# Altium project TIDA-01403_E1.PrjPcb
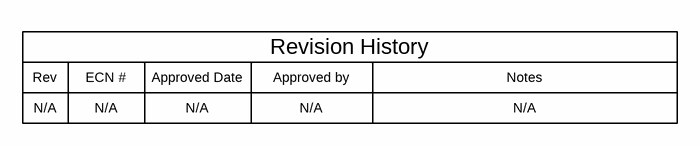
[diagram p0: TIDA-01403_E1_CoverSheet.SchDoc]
TID: TIDA-01403; TechSupport: http://www.ti.com/support; SCH_Rev: E1; PRJ_Title: 74-dB SNR, 10-MSPS, 14-Bit, Analog Front-End Reference Design for QVGA Resolution Thermal Imaging Cameras; PRJ_Number: TIDA-01403; PRJ_Engineer: Sharad Yadav; PRJ_Customer: Public Release; PCB_Rev: E1; PCB_Layout: Sharad Yadav; CopyrightYear: 2017
4 sheets, 161 parts. Net scope: flat (ports and power ports of the same name join across sheets).
Board file: TIDA-01403_E1.PcbDoc
Sheets:
  TIDA-01403_E1_CoverSheet.SchDoc
  TIDA-01403_E1_SchSheet_2.SchDoc
  TIDA-01403_E1_EVM_Hardware.SchDoc
  TIDA-01403_E1_SchSheet_1.SchDoc

## Sheet TIDA-01403_E1_CoverSheet.SchDoc: System Block Diagram
size 431 x 279 mm; Date: Not shown in title block; ApprovedBy: Not shown in title block; CheckedBy: Not shown in title block; Author: Not shown in title block; CompanyName: Not shown in title block; DrawnBy: Sharad Yadav; Engineer: Not shown in title block; Organization: Not shown in title block; Address1: Not shown in title block; Address2: Not shown in title block; Address3: Not shown in title block; Address4: Not shown in title block; DocumentNumber: 1; Revision: Use project parameter SCH_Rev; SheetNumber: 1; SheetTotal: 4; PageSetup: Record=PageOptions¦CenterHorizontal=True¦CenterVertical=True¦PrintScale=1.00¦XCorrection=1.00¦YCorrection=1.00¦PrintKind=0¦BorderSize=5000000¦LeftOffset=0¦BottomOffset=0¦Orientation=2¦PaperLength=1000¦PaperWidth=1000¦Scale=100¦PaperSource=15¦PrintQuality=600¦MediaType=1¦DitherType=10¦PaperKind=Letter¦PrintScaleMode=1

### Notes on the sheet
- Rev
- N/A
- ECN #
- Approved Date
- Approved by
- Revision History
- Notes

## Sheet TIDA-01403_E1_SchSheet_2.SchDoc: LDO, Status LEDs and Connectors
size 431 x 279 mm; Date: Not shown in title block; ApprovedBy: Not shown in title block; CheckedBy: Not shown in title block; Author: Not shown in title block; CompanyName: Not shown in title block; DrawnBy: Sharad Yadav; Engineer: Not shown in title block; Organization: Not shown in title block; Address1: Not shown in title block; Address2: Not shown in title block; Address3: Not shown in title block; Address4: Not shown in title block; DocumentNumber: 1; Revision: Use project parameter SCH_Rev; SheetNumber: 3; SheetTotal: 4; PageSetup: Record=PageOptions¦CenterHorizontal=True¦CenterVertical=True¦PrintScale=1.00¦XCorrection=1.00¦YCorrection=1.00¦PrintKind=0¦BorderSize=5000000¦LeftOffset=0¦BottomOffset=0¦Orientation=2¦PaperLength=1000¦PaperWidth=1000¦Scale=100¦PaperSource=15¦PrintQuality=600¦MediaType=1¦DitherType=10¦PaperKind=Letter¦PrintScaleMode=1
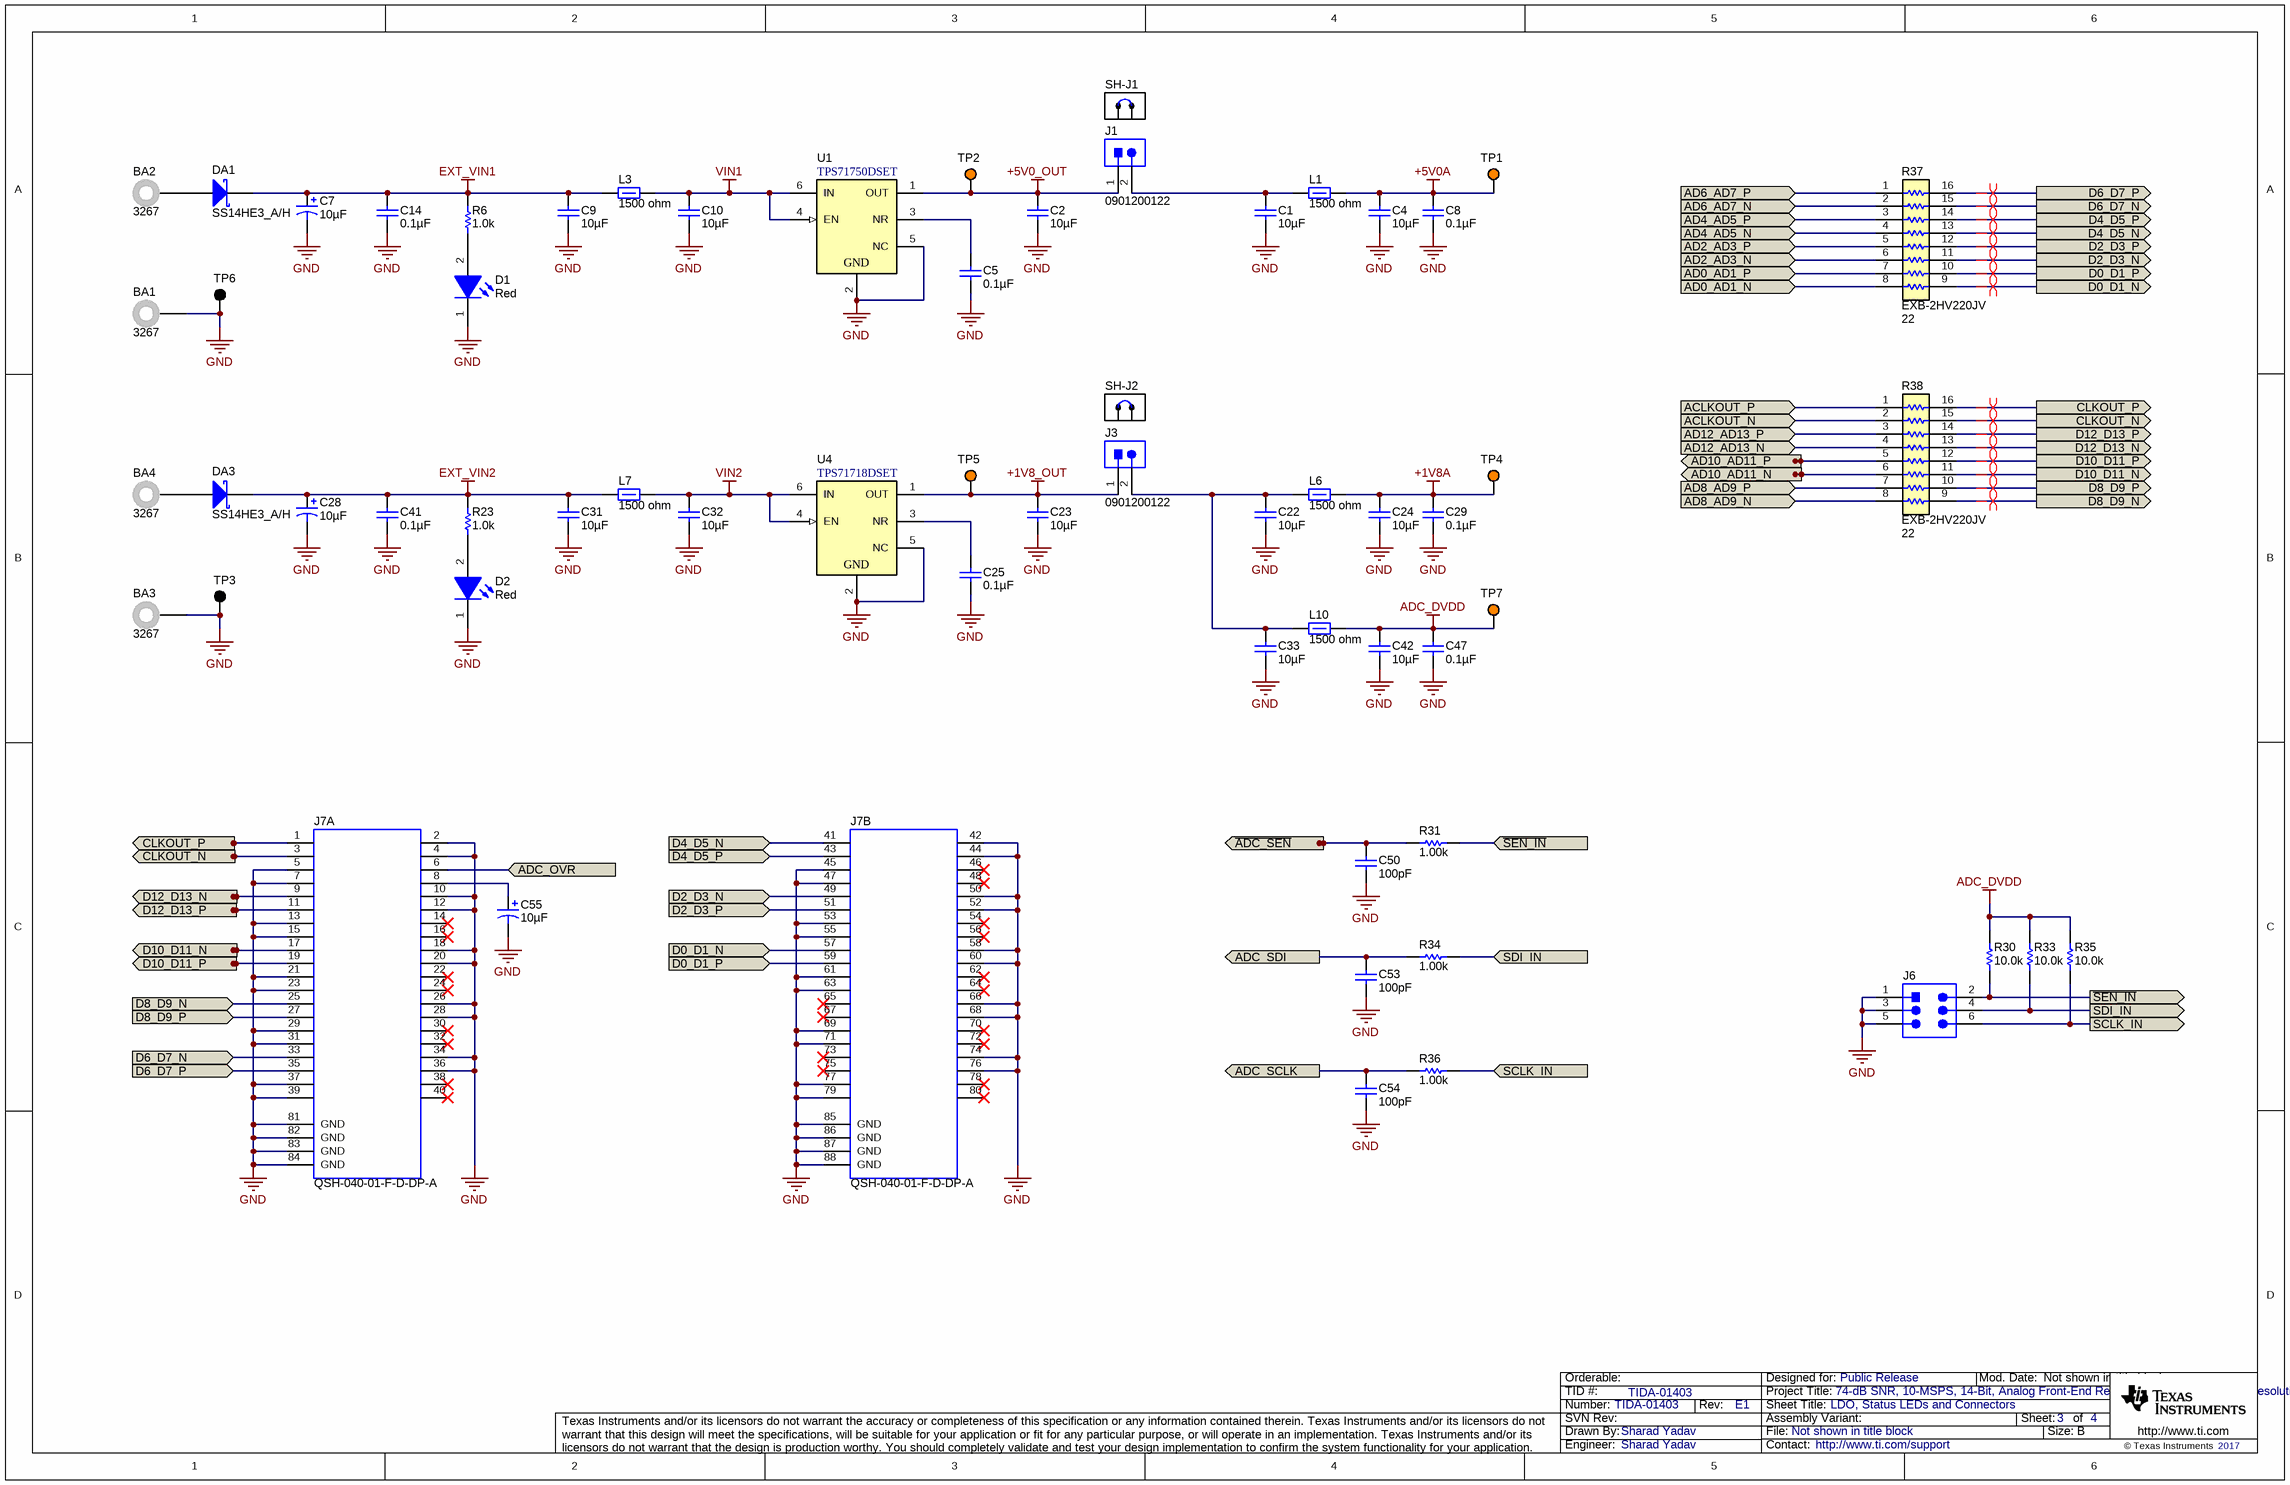
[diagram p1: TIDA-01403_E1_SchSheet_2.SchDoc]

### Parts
(Parts that share a designator on the sheet are numbered #1, #2 ... from top to bottom, then left to right.)
BA1  3267  [Pomona_3267]
BA2  3267  [Pomona_3267]
BA3  3267  [Pomona_3267]
BA4  3267  [Pomona_3267]
C1  ValueDisplayed: 10µF  [0805_HV]  (hidden comment: EMK212BB7106MG-T)
C2  ValueDisplayed: 10µF  [0805_HV]  (hidden comment: EMK212BB7106MG-T)
C4  ValueDisplayed: 10µF  [0805_HV]  (hidden comment: EMK212BB7106MG-T)
C5  ValueDisplayed: 0.1µF  [0402S]  (hidden comment: GRM155R71E104KE14D)
C7  ValueDisplayed: 10µF  [6032-28]  (hidden comment: 593D106X9016C2TE3)
C8  ValueDisplayed: 0.1µF  [0402S]  (hidden comment: GRM155R71C104KA88D)
C9  ValueDisplayed: 10µF  [0805_HV]  (hidden comment: EMK212BB7106MG-T)
C10  ValueDisplayed: 10µF  [0805_HV]  (hidden comment: EMK212BB7106MG-T)
C14  ValueDisplayed: 0.1µF  [0402S]  (hidden comment: GRM155R71C104KA88D)
C22  ValueDisplayed: 10µF  [0805_HV]  (hidden comment: EMK212BB7106MG-T)
C23  ValueDisplayed: 10µF  [0805_HV]  (hidden comment: EMK212BB7106MG-T)
C24  ValueDisplayed: 10µF  [0805_HV]  (hidden comment: EMK212BB7106MG-T)
C25  ValueDisplayed: 0.1µF  [0402S]  (hidden comment: GRM155R71E104KE14D)
C28  ValueDisplayed: 10µF  [6032-28]  (hidden comment: 593D106X9016C2TE3)
C29  ValueDisplayed: 0.1µF  [0402S]  (hidden comment: GRM155R71C104KA88D)
C31  ValueDisplayed: 10µF  [0805_HV]  (hidden comment: EMK212BB7106MG-T)
C32  ValueDisplayed: 10µF  [0805_HV]  (hidden comment: EMK212BB7106MG-T)
C33  ValueDisplayed: 10µF  [0805_HV]  (hidden comment: EMK212BB7106MG-T)
C41  ValueDisplayed: 0.1µF  [0402S]  (hidden comment: GRM155R71C104KA88D)
C42  ValueDisplayed: 10µF  [0805_HV]  (hidden comment: EMK212BB7106MG-T)
C47  ValueDisplayed: 0.1µF  [0402S]  (hidden comment: GRM155R71C104KA88D)
C50  ValueDisplayed: 100pF  [0402S]  (hidden comment: CC0402KRX7R9BB101)
C53  ValueDisplayed: 100pF  [0402S]  (hidden comment: CC0402KRX7R9BB101)
C54  ValueDisplayed: 100pF  [0402S]  (hidden comment: CC0402KRX7R9BB101)
C55  ValueDisplayed: 10µF  [6032-28]  (hidden comment: 593D106X9016C2TE3)
D1  value Red  [WL-SMCW_RED]  (hidden comment: 150060RS75000)
D2  value Red  [WL-SMCW_RED]  (hidden comment: 150060RS75000)
DA1  SS14HE3_A/H  [SMA]
DA3  SS14HE3_A/H  [SMA]
J1  0901200122  [TE_5-146278-2]
J3  0901200122  [TE_5-146278-2]
J6  TSW-103-07-G-D  [TSW-103-07-G-D]  (value not drawn)
J7  QSH-040-01-F-D-DP-A  [SAMTEC_QSH-040-01-F-D-DP-A]  (parts A,B of 2)
L1  ValueDisplayed: 1500 ohm  [0805_HV]  (hidden comment: 742792097)
L3  ValueDisplayed: 1500 ohm  [0805]  (hidden comment: 742792097)
L6  ValueDisplayed: 1500 ohm  [0805_HV]  (hidden comment: 742792097)
L7  ValueDisplayed: 1500 ohm  [0805]  (hidden comment: 742792097)
L10  ValueDisplayed: 1500 ohm  [0805_HV]  (hidden comment: 742792097)
R6  ValueDisplayed: 1.0k  [0402S]  (hidden comment: CRCW04021K00JNED)
R23  ValueDisplayed: 1.0k  [0402S]  (hidden comment: CRCW04021K00JNED)
R30  ValueDisplayed: 10.0k  [0402S]  (hidden comment: CRCW040210K0FKED)
R31  ValueDisplayed: 1.00k  [0402S]  (hidden comment: CRCW04021K00FKED)
R33  ValueDisplayed: 10.0k  [0402S]  (hidden comment: CRCW040210K0FKED)
R34  ValueDisplayed: 1.00k  [0402S]  (hidden comment: CRCW04021K00FKED)
R35  ValueDisplayed: 10.0k  [0402S]  (hidden comment: CRCW040210K0FKED)
R36  ValueDisplayed: 1.00k  [0402S]  (hidden comment: CRCW04021K00FKED)
R37  EXB-2HV220JV  ValueDisplayed: 22  [RESCAXS_EXB-2HV]
R38  EXB-2HV220JV  ValueDisplayed: 22  [RESCAXS_EXB-2HV]
SH-J1#1  969102-0000-DA  [SNT-100-BK-G]  (value not drawn)
SH-J2#1  969102-0000-DA  [SNT-100-BK-G]  (value not drawn)
TP1  5003  [Keystone5003]  (value not drawn)
TP2  5003  [Keystone5003]  (value not drawn)
TP3  5001  [Keystone5001]  (value not drawn)
TP4  5003  [Keystone5003]  (value not drawn)
TP5  5003  [Keystone5003]  (value not drawn)
TP6  5001  [Keystone5001]  (value not drawn)
TP7  5003  [Keystone5003]  (value not drawn)
U1  TPS71750DSET  [DSE0006A]
U4  TPS71718DSET  [DSE0006A]

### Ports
ACLKOUT_N (in), ACLKOUT_P (in), AD0_AD1_N (in), AD0_AD1_P (in), AD2_AD3_N (in), AD2_AD3_P (in), AD4_AD5_N (in), AD4_AD5_P (in), AD6_AD7_N (in), AD6_AD7_P (in), AD8_AD9_N (in), AD8_AD9_P (in), AD10_AD11_N (in), AD10_AD11_P (in), AD12_AD13_N (in), AD12_AD13_P (in), ADC_OVR (in), ADC_SCLK (out), ADC_SDI (out), CLKOUT_N (in), CLKOUT_N (out), CLKOUT_P (in), CLKOUT_P (out), D0_D1_N (in), D0_D1_N (out), D0_D1_P (in), D0_D1_P (out), D2_D3_N (in), D2_D3_N (out), D2_D3_P (in), D2_D3_P (out), D4_D5_N (in), D4_D5_N (out), D4_D5_P (in), D4_D5_P (out), D6_D7_N (in), D6_D7_N (out), D6_D7_P (in), D6_D7_P (out), D8_D9_N (in), D8_D9_N (out), D8_D9_P (in), D8_D9_P (out), D10_D11_N (in), D10_D11_N (out), D10_D11_P (in), D10_D11_P (out), D12_D13_N (in), D12_D13_N (out), D12_D13_P (in), D12_D13_P (out), SCLK_IN (in), SCLK_IN (out), SDI_IN (in), SDI_IN (out), ~{ADC_SEN} (out), ~{SEN_IN} (in), ~{SEN_IN} (out)

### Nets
+1V8_OUT: C23.1 J3.1 TP5.1 U4.1(OUT)
+1V8A: C24.1 C29.1 L6.2 TP4.1
+5V0_OUT: C2.1 J1.1 TP2.1 U1.1(OUT)
+5V0A: C4.1 C8.1 L1.2 TP1.1
ADC_DVDD: C42.1 C47.1 L10.2 R30.2 R33.2 R35.2 TP7.1
EXT_VIN1: C7.1(+) C9.1 C14.1 DA1.1(K) L3.1 R6.1
EXT_VIN2: C28.1(+) C31.1 C41.1 DA3.1(K) L7.1 R23.1
GND: BA1.1 BA3.1 C1.2 C2.2 C4.2 C5.2 C7.2(-) C8.2 C9.2 C10.2 C14.2 C22.2 C23.2 C24.2 C25.2 C28.2(-) C29.2 C31.2 C32.2 C33.2 C41.2 C42.2 C47.2 C50.2 C53.2 C54.2 C55.2(-) D1.1(K) D2.1(K) J6.1 J6.3 J6.5 J7.2 J7.4 J7.5 J7.7 J7.10 J7.12 J7.13 J7.15 J7.18 J7.20 J7.21 J7.23 J7.26 J7.28 J7.29 J7.31 J7.34 J7.36 J7.37 J7.39 J7.42 J7.44 J7.45 J7.47 J7.50 J7.52 J7.53 J7.55 J7.58 J7.60 J7.61 J7.63 J7.66 J7.68 J7.69 J7.71 J7.74 J7.76 J7.77 J7.79 J7.81(GND) J7.82(GND) J7.83(GND) J7.84(GND) J7.85(GND) J7.86(GND) J7.87(GND) J7.88(GND) TP3.1 TP6.1 U1.2(GND) U1.5(NC) U4.2(GND) U4.5(NC)
VIN1: C10.1 L3.2 U1.4(EN) U1.6(IN)
VIN2: C32.1 L7.2 U4.4(EN) U4.6(IN)
~{ADC_SEN}: C50.1 R31.1 ; port ~{ADC_SEN}
~{SEN_IN}: J6.2 R30.1 R31.2 ; port ~{SEN_IN}
ACLKOUT_N: R38.2 ; port ACLKOUT_N
ACLKOUT_P: R38.1 ; port ACLKOUT_P
AD0_AD1_N: R37.8 ; port AD0_AD1_N
AD0_AD1_P: R37.7 ; port AD0_AD1_P
AD2_AD3_N: R37.6 ; port AD2_AD3_N
AD2_AD3_P: R37.5 ; port AD2_AD3_P
AD4_AD5_N: R37.4 ; port AD4_AD5_N
AD4_AD5_P: R37.3 ; port AD4_AD5_P
AD6_AD7_N: R37.2 ; port AD6_AD7_N
AD6_AD7_P: R37.1 ; port AD6_AD7_P
AD8_AD9_N: R38.8 ; port AD8_AD9_N
AD8_AD9_P: R38.7 ; port AD8_AD9_P
AD10_AD11_N: R38.6 ; port AD10_AD11_N
AD10_AD11_P: R38.5 ; port AD10_AD11_P
AD12_AD13_N: R38.4 ; port AD12_AD13_N
AD12_AD13_P: R38.3 ; port AD12_AD13_P
ADC_OVR: J7.6 ; port ADC_OVR
ADC_SCLK: C54.1 R36.1 ; port ADC_SCLK
ADC_SDI: C53.1 R34.1 ; port ADC_SDI
CLKOUT_N: J7.3 R38.15 ; port CLKOUT_N
CLKOUT_P: J7.1 R38.16 ; port CLKOUT_P
D0_D1_N: J7.57 R37.9 ; port D0_D1_N
D0_D1_P: J7.59 R37.10 ; port D0_D1_P
D2_D3_N: J7.49 R37.11 ; port D2_D3_N
D2_D3_P: J7.51 R37.12 ; port D2_D3_P
D4_D5_N: J7.41 R37.13 ; port D4_D5_N
D4_D5_P: J7.43 R37.14 ; port D4_D5_P
D6_D7_N: J7.33 R37.15 ; port D6_D7_N
D6_D7_P: J7.35 R37.16 ; port D6_D7_P
D8_D9_N: J7.25 R38.9 ; port D8_D9_N
D8_D9_P: J7.27 R38.10 ; port D8_D9_P
D10_D11_N: J7.17 R38.11 ; port D10_D11_N
D10_D11_P: J7.19 R38.12 ; port D10_D11_P
D12_D13_N: J7.9 R38.13 ; port D12_D13_N
D12_D13_P: J7.11 R38.14 ; port D12_D13_P
SCLK_IN: J6.6 R35.1 R36.2 ; port SCLK_IN
SDI_IN: J6.4 R33.1 R34.2 ; port SDI_IN
NetBA2_1: BA2.1 DA1.2(A)
NetBA4_1: BA4.1 DA3.2(A)
NetC1_1: C1.1 J1.2 L1.1
NetC5_1: C5.1 U1.3(NR)
NetC22_1: C22.1 C33.1 J3.2 L6.1 L10.1
NetC25_1: C25.1 U4.3(NR)
NetC55_1: C55.1(+) J7.8
NetD1_2: D1.2(A) R6.2
NetD2_2: D2.2(A) R23.2

Not connected (* = marked no-connect by the designer): J7 14* 16* 22* 24* 30* 32* 38* 40* 46* 48* 54* 56* 62* 64* 65* 67* 70* 72* 73* 75* 78* 80*

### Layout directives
differential pair: CLKOUT_N, CLKOUT_P, D0_D1_N, D0_D1_P, D2_D3_N, D2_D3_P, D4_D5_N, D4_D5_P, D6_D7_N, D6_D7_P, D8_D9_N, D8_D9_P, D10_D11_N, D10_D11_P, D12_D13_N, D12_D13_P

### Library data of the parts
BA1-BA4 = CMP-0055388-2: Standard Banana Jack, Uninsulated; Manufacturer: Pomona Electronics; CT: TRUE; Green_REACh: Incomplete; CNHeader: FALSE; Green_Lifecycle: Not Set
C1 C2 C4 C9 C10 C22-C24 C31-C33 C42 = GRM21BZ71E106KE15L: CAP, CERM, 10 µF, 16 V, +/- 10%, X7R, 0805; Manufacturer: Taiyo Yuden; Polarized: N; CompType: Capacitor; Value: 10uF; U/M: EA; Cap_F: 0.00001; Tolerance_%: 10; Value1: Unknown; VDC_V: 16V; TaMin_C: -55; TaMax_C: 125; Cap_Case: 0805; SizeArea_mm2: 2.5; SizeAreaWB_mm2: 6.75; SizeX_mm: 2; SizeY_mm: 1.25; SizeZ_mm: 1.45; AEC Category: Q200
C5 C25 = GRM155R71E104KE14D: CAP, CERM, 0.1 µF, 25 V, +/- 10%, X7R, 0402; Manufacturer: MuRata; Polarized: N; CompType: Capacitor; Value: 0.1uF; U/M: EA; Cap_F: 0.0000001; Tolerance_%: 10; Value1: Unknown; VDC_V: 25; Value2: 25V; TaMin_C: -55; TaMax_C: 125; Cap_Case: 0402; SizeArea_mm2: 0.5; SizeAreaWB_mm2: 3; SizeX_mm: 1; SizeZ_mm: 0.6; AEC Category: Q200
C7 C28 C55 = 593D106X9016C2TE3: CAP, TA, 10 µF, 16 V, +/- 10%, 0.45 ohm, SMD; Manufacturer: Vishay-Sprague; Polarized: Y; CompType: Capacitor; Value: 10uF; U/M: EA; Cap_F: 0.00001; Tolerance_%: 10; VDC_V: 16; Value2: 16V; ESR_ohm: 0.45; IRMS_A: 0.49; TaMin_C: -55; TaMax_C: 125; Cap_Case: C; SizeAreaWB_mm2: 41.6; SizeArea_mm2: 19.2; SizeX_mm: 6; SizeY_mm: 3.2; SizeZ_mm: 2.8; AEC Category: Q200
C8 C14 C29 C41 C47 = GRM155R71C104KA88D: CAP, CERM, 0.1 µF, 16 V, +/- 10%, X7R, 0402; Manufacturer: MuRata; Polarized: N; CompType: Capacitor; Value: 0.1uF; U/M: EA; Cap_F: 0.0000001; Tolerance_%: 10; Value1: Unknown; VDC_V: 16; Value2: 16V; TaMin_C: -55; TaMax_C: 125; Cap_Case: 0402; SizeArea_mm2: 0.5; SizeAreaWB_mm2: 3; SizeX_mm: 1; SizeZ_mm: 0.6; AEC Category: Q200
C50 C53 C54 = CC0402KRX7R9BB101: CAP, CERM, 100 pF, 50 V, +/- 10%, X7R, 0402; Manufacturer: Yageo America; Polarized: N; CompType: Capacitor; Value: 100pF; U/M: EA; Cap_F: 0.0000000001; Tolerance_%: 10; Value1: Unknown; VDC_V: 50; Value2: 50V; TaMin_C: -55; TaMax_C: 125; Cap_Case: 0402; SizeArea_mm2: 0.5; SizeAreaWB_mm2: 3; SizeX_mm: 1; SizeZ_mm: 0.6; AEC Category: Q200
D1 D2 = 150060RS75000: LED, Red, SMD; Manufacturer: Wurth Elektronik; Type: AlInGaP; Vf_V: 2; Value2: 2V; Io_A: 0.03; Vr_V: 5; Tjmax_C: 85; Power_TotalModule: 0.072; Value1: 0.072W; Angle: 140; U/M: EA
DA1 DA3 = SS14HE3_A/H: Diode, Schottky, 40 V, 1 A, AEC-Q101, SMA; Manufacturer: Vishay-Semiconductor; U/M: EA; Vf_V: 0.5; Value: 40V; Value1: 1A; Value2: 0.5V; Io_A: 1; Vr_V: 40; TJmax_C: 150; SizeAreaWB_mm2: 37.3428; SizeArea_mm2: 16.3228; SizeX_mm: 5.59; SizeY_mm: 2.92; SizeZ_mm: 2.87; AEC Category: Q101; AEC Qualified: Y
J1 J3 = 5-146278-2: Header, 100mil, 2x1, Tin, TH; Manufacturer: Molex Connector Corporation; SymbolCreator: a0412235
J6 = TSW-103-07-G-D: Header, 100mil, 3x2, Gold, TH; Manufacturer: Samtec; SymbolCreator: a0412235; Pitch_mm: 2.54; Gender: Male; Shrouded: N; Row_Count: 2; Current_A: 6.3; Voltage_V: 550; Cert_CSA: Y
J7 = QSH-040-01-F-D-DP-A: Socket, 40x2, Gold, SMD; Manufacturer: Samtec; SymbolCreator: Altium
L1 L3 L6 L7 L10 = 742792097: Ferrite Bead, 1500 ohm @ 100 MHz, 1 A, 0805; Manufacturer: Wurth Elektronik; Imax_A: 1; DCR_ohm: 0.3; Value1: 0.3 ohm; Value2: 1A; SizeAreaWB_mm2: 6.75; SizeArea_mm2: 2.5; SizeX_mm: 2; SizeY_mm: 1.25; SizeZ_mm: 1.45; ZTyp@100MHz_Ohm: 1500; Ztyp@1GHz_Ohm: 150.538
R6 R23 = CRCW04021K00JNED: RES, 1.0 k, 5%, 0.063 W, 0402; Manufacturer: Vishay-Dale; CompType: Resistor; Value: 1.0k; Res_ohm: 1000; Value_Code: 1k00; Tolerance_%: 5; Power_W: 0.063; Value2: 0.063W; VDC_V: 50; TempCo: 200 ppm/C; SizeArea_mm2: 0.5; SizeX_mm: 1; SizeZ_mm: 0.6; EIA_Code: E24; U/M: EA; AEC Category: Q200
R30 R33 R35 = CRCW040210K0FKED: RES, 10.0 k, 1%, 0.063 W, 0402; Manufacturer: Vishay-Dale; CompType: Resistor; Value: 10.0k; Res_ohm: 10000; Value_Code: 10k0; Tolerance_%: 1; Power_W: 0.063; Value2: 0.063W; VDC_V: 50; TempCo: 100 ppm/C; SizeArea_mm2: 0.5; SizeZ_mm: 0.6; EIA_Code: E96; U/M: EA; AEC Category: Q200
R31 R34 R36 = CRCW04021K00FKED: RES, 1.00 k, 1%, 0.063 W, 0402; Manufacturer: Vishay-Dale; CompType: Resistor; Value: 1.00k; Res_ohm: 1000; Value_Code: 1k00; Tolerance_%: 1; Power_W: 0.063; Value2: 0.063W; VDC_V: 50; TempCo: 100 ppm/C; SizeArea_mm2: 0.5; SizeZ_mm: 0.6; EIA_Code: E96; U/M: EA; AEC Category: Q200
R37 R38 = EXB-2HV220JV: RES, 22, 5%, 0.0625 W, Resistor Array - 8x1; Manufacturer: Panasonic; SymbolCreator: a0411947; Value: 22; Value_Code: 22R0; Tolerance_%: 5; Power_W: 0.0625; TempCo: 200 ppm/C; EIA_Code: E24; U/M: EA; AEC Category: Q200
SH-J1#1 SH-J2#1 = 969102-0000-DA: Shunt, 100mil, Gold plated, Black; Manufacturer: 3M; Alternate Manufacturer: Samtec; Value: 1x2; Note: You can "mate" this to a header by matching the designator.  i.e. use SH-J3 for header J3
TP1 TP2 TP4 TP5 TP7 = 5003: Test Point, Miniature, Orange, TH; Manufacturer: Keystone; CompType: Test Point Loop; ContactFinish: Silver
TP3 TP6 = 5001: Test Point, Miniature, Black, TH; Manufacturer: Keystone; CompType: Test Point Loop; ContactFinish: Silver
U1 = TPS71750DSET: Single Output High PSRR LDO, 150 mA, Fixed 5 V Output, 2.5 to 6.5 V Input, with Low IQ, 6-pin WSON (DSE), -40 to 125 degC, Green (RoHS & no Sb/Br); Manufacturer: Texas Instruments; Alternate PartNumber: Equivalent; Accuracy(%): 3; Fixed Output Options(V): 5; Iout(Max)(A): 0.15; Iq(Typ)(mA): 0.05; SubFamily: Single Channel LDO; Vdo(Typ)(mV): 170; Vin(Max)(V): 6.5; Vin(Min)(V): 2.5
U4 = TPS71718DSET: Single Output High PSRR LDO, 150 mA, Fixed 1.8 V Output, 2.5 to 6.5 V Input, with Low IQ, 6-pin WSON (DSE), -40 to 125 degC, Green (RoHS & no Sb/Br); Manufacturer: Texas Instruments; Alternate PartNumber: Equivalent; Accuracy(%): 3; Fixed Output Options(V): 1.8; Iout(Max)(A): 0.15; Iq(Typ)(mA): 0.05; SubFamily: Single Channel LDO; Vdo(Typ)(mV): 170; Vin(Max)(V): 6.5; Vin(Min)(V): 2.5

## Sheet TIDA-01403_E1_EVM_Hardware.SchDoc: Hardware
size 431 x 279 mm; Date: Not shown in title block; ApprovedBy: Not shown in title block; CheckedBy: Not shown in title block; Author: Not shown in title block; CompanyName: Not shown in title block; DrawnBy: Sharad Yadav; Engineer: Not shown in title block; Organization: Not shown in title block; Address1: Not shown in title block; Address2: Not shown in title block; Address3: Not shown in title block; Address4: Not shown in title block; DocumentNumber: 1; Revision: Use project parameter SCH_Rev; SheetNumber: 4; SheetTotal: 4; PageSetup: Record=PageOptions¦CenterHorizontal=True¦CenterVertical=True¦PrintScale=1.00¦XCorrection=1.00¦YCorrection=1.00¦PrintKind=0¦BorderSize=5000000¦LeftOffset=0¦BottomOffset=0¦Orientation=2¦PaperLength=1000¦PaperWidth=1000¦Scale=100¦PaperSource=15¦PrintQuality=600¦MediaType=1¦DitherType=10¦PaperKind=Letter¦PrintScaleMode=1
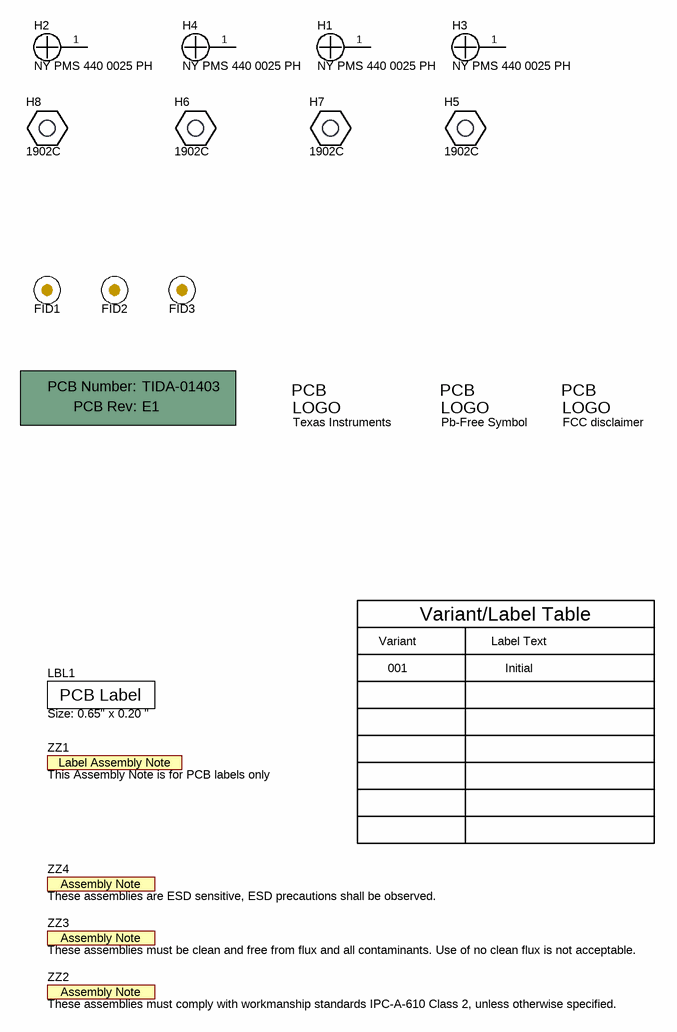
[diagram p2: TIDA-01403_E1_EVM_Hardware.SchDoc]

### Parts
!PCB1  Printed Circuit Board  (value not drawn)  (mechanical)
FID1  Fiducial  [Fiducial10-20]  (value not drawn)
FID2  Fiducial  [Fiducial10-20]  (value not drawn)
FID3  Fiducial  [Fiducial10-20]  (value not drawn)
H1  NY PMS 440 0025 PH  [NY PMS 440 0025 PH]
H2  NY PMS 440 0025 PH  [NY PMS 440 0025 PH]
H3  NY PMS 440 0025 PH  [NY PMS 440 0025 PH]
H4  NY PMS 440 0025 PH  [NY PMS 440 0025 PH]
H5  1902C  [Keystone_1902C]
H6  1902C  [Keystone_1902C]
H7  1902C  [Keystone_1902C]
H8  1902C  [Keystone_1902C]
LBL1  Size: 0.65" x 0.20 "  [Label_650x200]
Logo1  Texas Instruments  [TI_Stacked_Overlay_Small]  (no BOM)
Logo2  Pb-Free Symbol  [Pb-Free_Overlay_Small]  (no BOM)
Logo3  FCC disclaimer  [FCC_disclaimer]  (no BOM)
ZZ1  This Assembly Note is for PCB labels only  [AssemblyNoteLabel]  (no BOM)
ZZ2  These assemblies must comply with workmanship standards IPC-A-610 Class 2, unless otherwise specified.  [AssemblyNote]  (no BOM)
ZZ3  These assemblies must be clean and free from flux and all contaminants. Use of no clean flux is not acceptable.  [AssemblyNote]  (no BOM)
ZZ4  These assemblies are ESD sensitive, ESD precautions shall be observed.  [AssemblyNote]  (no BOM)

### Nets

Not connected (* = marked no-connect by the designer): H1 1; H2 1; H3 1; H4 1

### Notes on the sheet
- Variant
- Variant/Label Table
- Label Text
- 001
- Initial

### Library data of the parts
!PCB1 = PCB: Manufacturer: Any; PartNumber: TIDA-01403; SymbolCreator: a0412235
FID1-FID3 = Fiducial: Fiducial mark.  There is nothing to buy or mount.; SymbolCreator: codlsc
H1-H4 = NY PMS 440 0025 PH: Machine Screw, Round, #4-40 x 1/4, Nylon, Philips panhead; Manufacturer: B&F Fastener Supply; CompType: Hardware; SymbolCreator: codlsc; U/M: EA
H5-H8 = 1902C: Standoff, Hex, 0.5"L #4-40 Nylon; Manufacturer: Keystone; CompType: Hardware
LBL1 = THT-14-423-10: Thermal Transfer Printable Labels, 0.650" W x 0.200" H - 10,000 per roll; Manufacturer: Brady; SymbolCreator: a0412235; CompType: Label
Logo1 = TI_Logo: Texas Instrument Corporate Signature; SymbolCreator: codlsc
Logo2 = Pb-Free: SymbolCreator: a0412235
Logo3 = FCC_disclaimer: SymbolCreator: codlsc
ZZ1 = AssemblyNoteLabel: SymbolCreator: a0412235
ZZ2-ZZ4 = AssemblyNote: SymbolCreator: codlsc

## Sheet TIDA-01403_E1_SchSheet_1.SchDoc: Driver Amplifier and ADC Circuitry
size 431 x 279 mm; Date: Not shown in title block; ApprovedBy: Not shown in title block; CheckedBy: Not shown in title block; Author: Not shown in title block; CompanyName: Not shown in title block; DrawnBy: Sharad Yadav; Engineer: Not shown in title block; Organization: Not shown in title block; Address1: Not shown in title block; Address2: Not shown in title block; Address3: Not shown in title block; Address4: Not shown in title block; DocumentNumber: 1; Revision: Use project parameter SCH_Rev; SheetNumber: 2; SheetTotal: 4; PageSetup: Record=PageOptions¦CenterHorizontal=True¦CenterVertical=True¦PrintScale=1.00¦XCorrection=1.00¦YCorrection=1.00¦PrintKind=0¦BorderSize=5000000¦LeftOffset=0¦BottomOffset=0¦Orientation=2¦PaperLength=1000¦PaperWidth=1000¦Scale=100¦PaperSource=15¦PrintQuality=600¦MediaType=1¦DitherType=10¦PaperKind=Letter¦PrintScaleMode=1
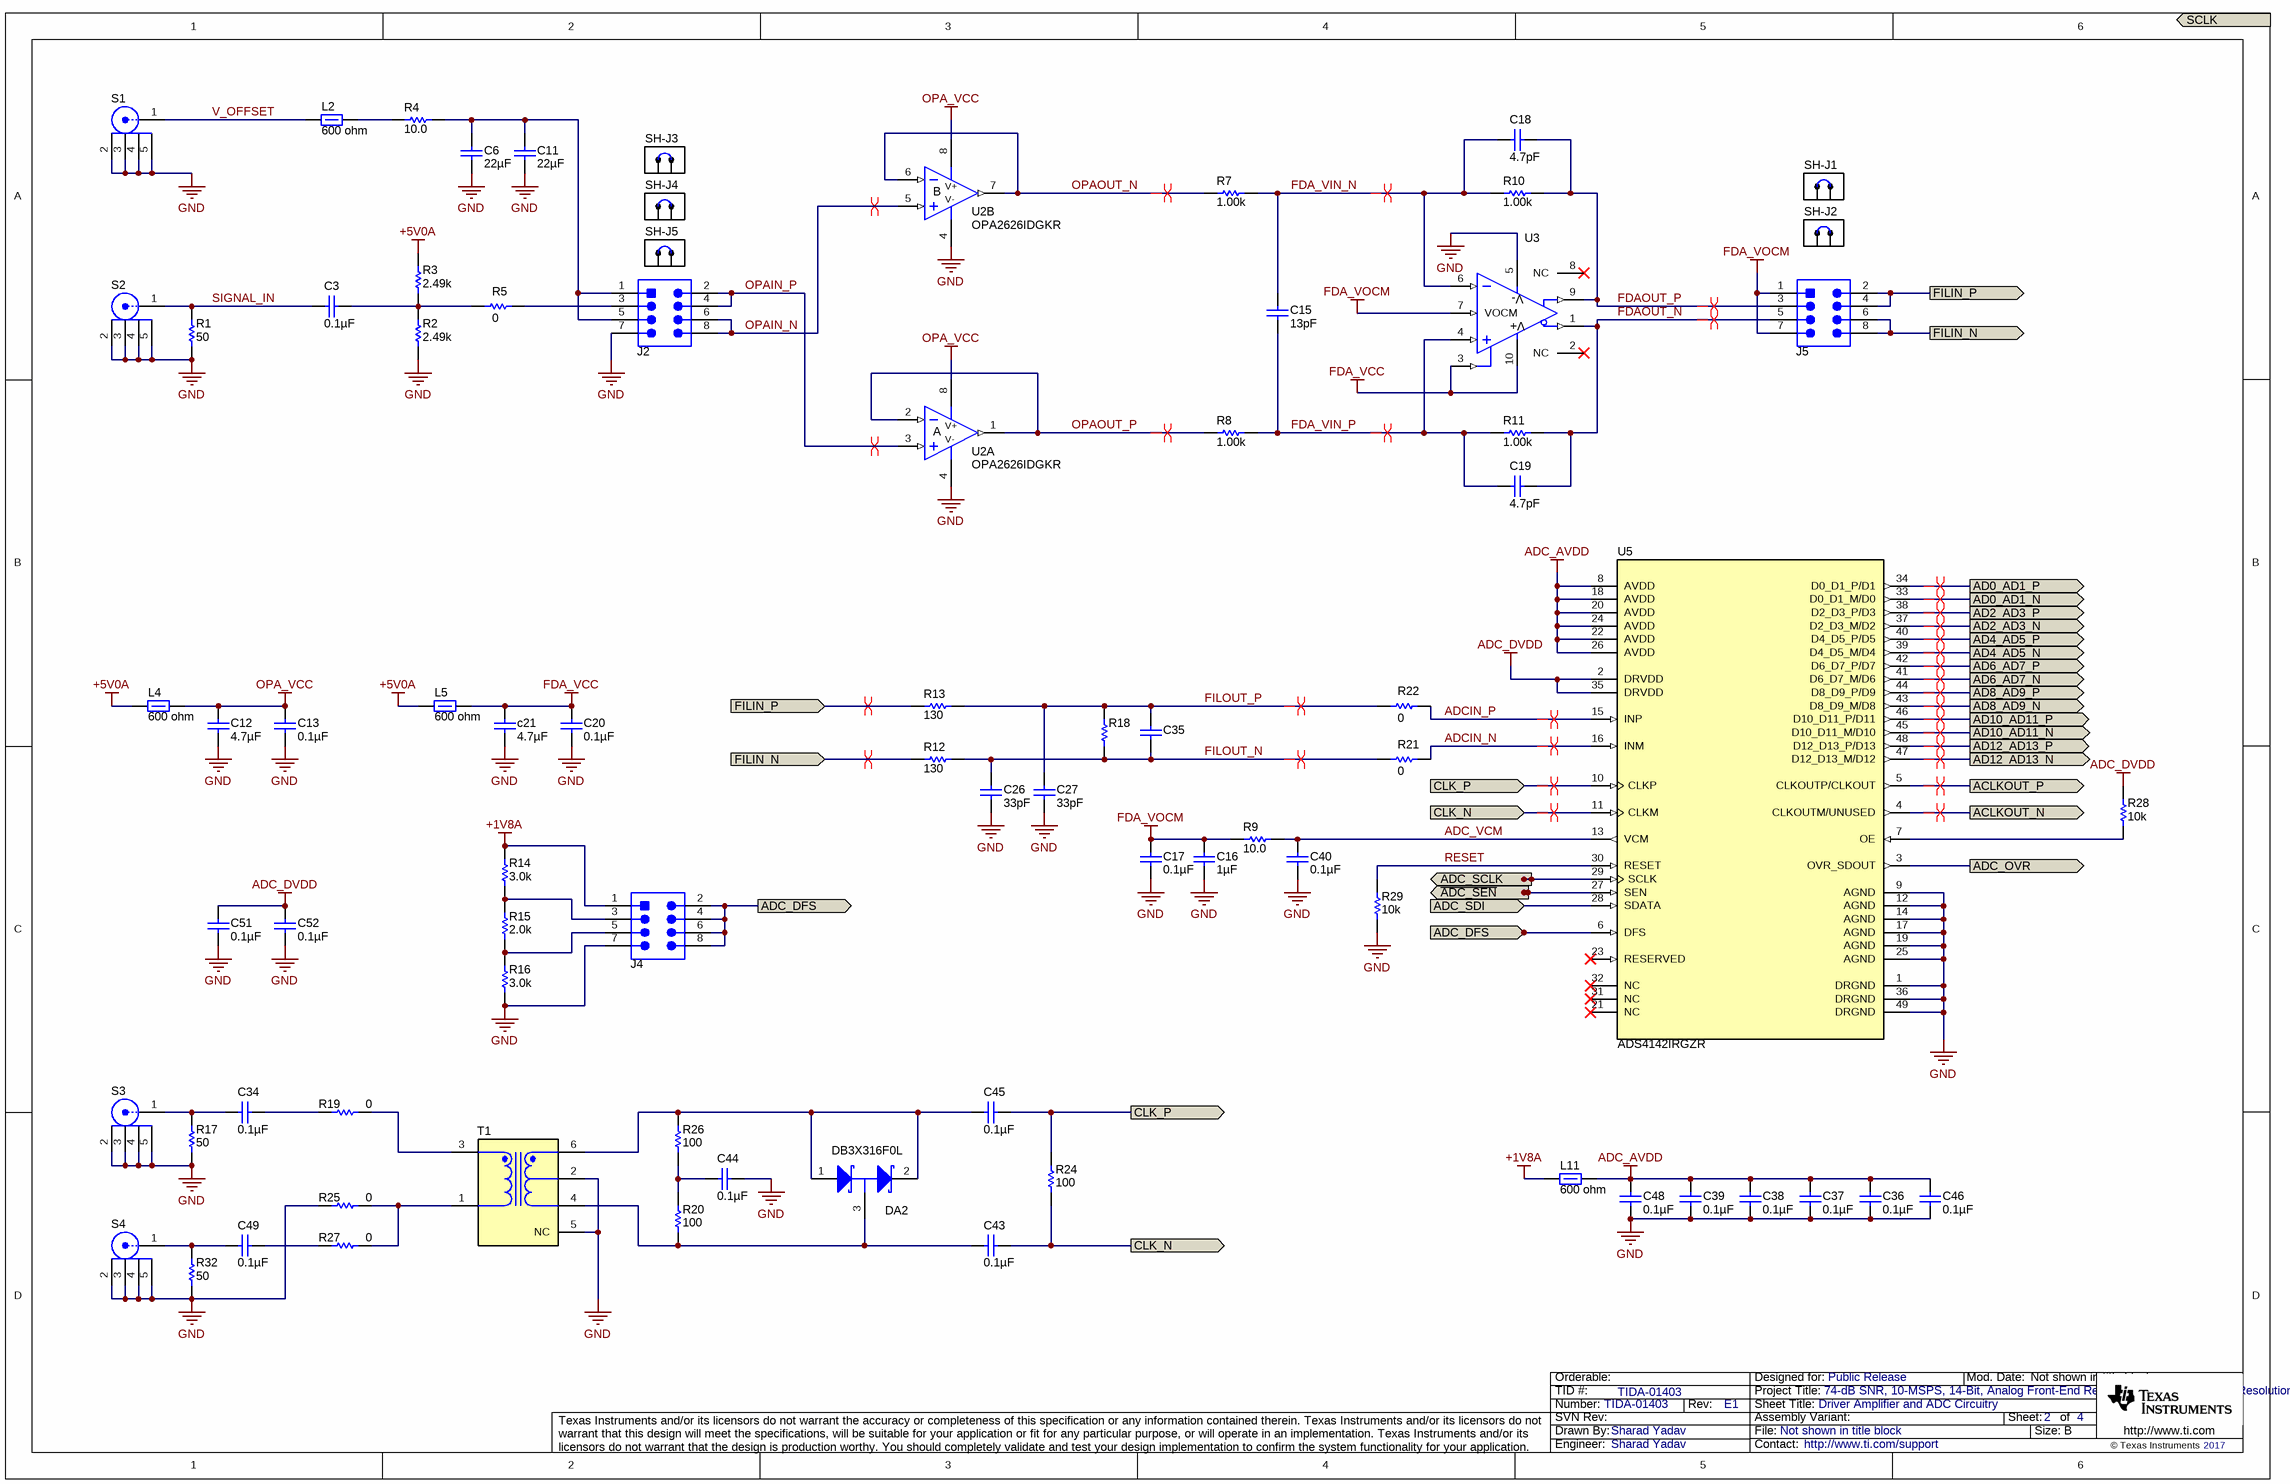
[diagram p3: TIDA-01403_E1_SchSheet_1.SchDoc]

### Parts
(Parts that share a designator on the sheet are numbered #1, #2 ... from top to bottom, then left to right.)
C3  ValueDisplayed: 0.1µF  [0402S]  (hidden comment: GRM155R71C104KA88D)
C6  ValueDisplayed: 22µF  [1206_180]  (hidden comment: LMK316AB7226KL-TR)
C11  ValueDisplayed: 22µF  [1206_180]  (hidden comment: LMK316AB7226KL-TR)
C12  ValueDisplayed: 4.7µF  [0402S]  (hidden comment: CL05A475MO5NUNC)
C13  ValueDisplayed: 0.1µF  [0402S]  (hidden comment: GRM155R71C104KA88D)
C15  ValueDisplayed: 13pF  [0402S]  (hidden comment: GRM1555C1H130JA01D)
C16  ValueDisplayed: 1µF  [0402S]  (hidden comment: GRM155R61E105KA12D)
C17  ValueDisplayed: 0.1µF  [0402S]  (hidden comment: GRM155R71E104KE14D)
C18  ValueDisplayed: 4.7pF  [0402S]  (hidden comment: GRM1555C1E4R7CA01D)
C19  ValueDisplayed: 4.7pF  [0402S]  (hidden comment: GRM1555C1E4R7CA01D)
C20  ValueDisplayed: 0.1µF  [0402S]  (hidden comment: GRM155R71C104KA88D)
c21  ValueDisplayed: 4.7µF  [0402S]  (hidden comment: CL05A475MO5NUNC)
C26  ValueDisplayed: 33pF  [0402S]  (hidden comment: 885012005043)
C27  ValueDisplayed: 33pF  [0402S]  (hidden comment: 885012005043)
C34  ValueDisplayed: 0.1µF  [0402S]  (hidden comment: GRM155R71C104KA88D)
C35  GRM1555C1H560JA01D  [0402S]  (value not drawn)
C36  ValueDisplayed: 0.1µF  [0402S]  (hidden comment: GRM155R71C104KA88D)
C37  ValueDisplayed: 0.1µF  [0402S]  (hidden comment: GRM155R71C104KA88D)
C38  ValueDisplayed: 0.1µF  [0402S]  (hidden comment: GRM155R71C104KA88D)
C39  ValueDisplayed: 0.1µF  [0402S]  (hidden comment: GRM155R71C104KA88D)
C40  ValueDisplayed: 0.1µF  [0402S]  (hidden comment: GRM155R71E104KE14D)
C43  ValueDisplayed: 0.1µF  [0402S]  (hidden comment: GRM155R71C104KA88D)
C44  ValueDisplayed: 0.1µF  [0402S]  (hidden comment: GRM155R71C104KA88D)
C45  ValueDisplayed: 0.1µF  [0402S]  (hidden comment: GRM155R71C104KA88D)
C46  ValueDisplayed: 0.1µF  [0402S]  (hidden comment: GRM155R71C104KA88D)
C48  ValueDisplayed: 0.1µF  [0402S]  (hidden comment: GRM155R71C104KA88D)
C49  ValueDisplayed: 0.1µF  [0402S]  (hidden comment: GRM155R71C104KA88D)
C51  ValueDisplayed: 0.1µF  [0402S]  (hidden comment: GRM155R71C104KA88D)
C52  ValueDisplayed: 0.1µF  [0402S]  (hidden comment: GRM155R71C104KA88D)
DA2  DB3X316F0L  [SOT-23]
J2  GRPB042VWVN-RC  [Sullins_GRPB042VWVN]  (value not drawn)
J4  GRPB042VWVN-RC  [Sullins_GRPB042VWVN]  (value not drawn)
J5  GRPB042VWVN-RC  [Sullins_GRPB042VWVN]  (value not drawn)
L2  ValueDisplayed: 600 ohm  [0402S]  (hidden comment: MMZ1005B601CTD25)
L4  ValueDisplayed: 600 ohm  [0402S]  (hidden comment: MMZ1005B601CTD25)
L5  ValueDisplayed: 600 ohm  [0402S]  (hidden comment: MMZ1005B601CTD25)
L11  ValueDisplayed: 600 ohm  [0402S]  (hidden comment: MMZ1005B601CTD25)
R1  ValueDisplayed: 50  [0603S]  (hidden comment: CRCW060350R0FKEA)
R2  ValueDisplayed: 2.49k  [0402S]  (hidden comment: CRCW04022K49FKED)
R3  ValueDisplayed: 2.49k  [0402S]  (hidden comment: CRCW04022K49FKED)
R4  ValueDisplayed: 10.0  [0402S]  (hidden comment: CRCW040210R0FKED)
R5  ValueDisplayed: 0  [0402S]  (hidden comment: ERJ-2GE0R00X)
R7  ValueDisplayed: 1.00k  [0402S]  (hidden comment: ERA-2AEB102X)
R8  ValueDisplayed: 1.00k  [0402S]  (hidden comment: ERA-2AEB102X)
R9  ValueDisplayed: 10.0  [0402S]  (hidden comment: CRCW040210R0FKED)
R10  ValueDisplayed: 1.00k  [0402S]  (hidden comment: ERA-2AEB102X)
R11  ValueDisplayed: 1.00k  [0402S]  (hidden comment: ERA-2AEB102X)
R12  ValueDisplayed: 130  [0402S]  (hidden comment: CRCW0402130RFKED)
R13  ValueDisplayed: 130  [0402S]  (hidden comment: CRCW0402130RFKED)
R14  ValueDisplayed: 3.0k  [0402S]  (hidden comment: CRCW04023K00JNED)
R15  ValueDisplayed: 2.0k  [0402S]  (hidden comment: CRCW04022K00JNED)
R16  ValueDisplayed: 3.0k  [0402S]  (hidden comment: CRCW04023K00JNED)
R17  ValueDisplayed: 50  [0603S]  (hidden comment: CRCW060350R0FKEA)
R18  MCR01MRTF1002  [0402S]  (value not drawn)
R19  ValueDisplayed: 0  [0402S]  (hidden comment: ERJ-2GE0R00X)
R20  ValueDisplayed: 100  [0402S]  (hidden comment: CRCW0402100RFKED)
R21  ValueDisplayed: 0  [0402S]  (hidden comment: ERJ-2GE0R00X)
R22  ValueDisplayed: 0  [0402S]  (hidden comment: ERJ-2GE0R00X)
R24  ValueDisplayed: 100  [0402S]  (hidden comment: CRCW0402100RFKED)
R25  ValueDisplayed: 0  [0402S]  (hidden comment: ERJ-2GE0R00X)
R26  ValueDisplayed: 100  [0402S]  (hidden comment: CRCW0402100RFKED)
R27  ValueDisplayed: 0  [0402S]  (hidden comment: ERJ-2GE0R00X)
R28  ValueDisplayed: 10k  [0402S]  (hidden comment: CRCW040210K0JNED)
R29  ValueDisplayed: 10k  [0402S]  (hidden comment: CRCW040210K0JNED)
R32  ValueDisplayed: 50  [0603S]  (hidden comment: CRCW060350R0FKEA)
S1  142-0711-821  [Johnson_142-0711-821]  (value not drawn)
S2  142-0711-821  [Johnson_142-0711-821]  (value not drawn)
S3  142-0711-821  [Johnson_142-0711-821]  (value not drawn)
S4  142-0711-821  [Johnson_142-0711-821]  (value not drawn)
SH-J1#2  M50-1900005  (value not drawn)  (mechanical)
SH-J2#2  M50-1900005  (value not drawn)  (mechanical)
SH-J3  M50-1900005  (value not drawn)  (mechanical)
SH-J4  M50-1900005  (value not drawn)  (mechanical)
SH-J5  M50-1900005  (value not drawn)  (mechanical)
T1  ADT1-1WT+  [MNC_CD542]  (value not drawn)
U2  OPA2626IDGKR  [DGK0008A_N]  (parts A,B of 2)
U3  THS4551IRUNR  [RUN0010A]  (value not drawn)
U5  ADS4142IRGZR  [RGZ0048D]

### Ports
ACLKOUT_N (out), ACLKOUT_P (out), AD0_AD1_N (out), AD0_AD1_P (out), AD2_AD3_N (out), AD2_AD3_P (out), AD4_AD5_N (out), AD4_AD5_P (out), AD6_AD7_N (out), AD6_AD7_P (out), AD8_AD9_N (out), AD8_AD9_P (out), AD10_AD11_N (out), AD10_AD11_P (out), AD12_AD13_N (out), AD12_AD13_P (out), ADC_DFS (in), ADC_DFS (out), ADC_OVR (out), ADC_SCLK (in), ADC_SDI (in), CLK_N (in), CLK_N (out), CLK_P (in), CLK_P (out), FILIN_N (in), FILIN_N (out), FILIN_P (in), FILIN_P (out), SCLK (out), ~{ADC_SEN} (in)

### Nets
+1V8A: J4.1 L11.1 R14.2
+5V0A: L4.1 L5.1 R3.2
ADC_AVDD: C36.1 C37.1 C38.1 C39.1 C46.1 C48.1 L11.2 U5.8(AVDD) U5.18(AVDD) U5.20(AVDD) U5.22(AVDD) U5.24(AVDD) U5.26(AVDD)
ADC_DVDD: C51.1 C52.1 R28.2 U5.2(DRVDD) U5.35(DRVDD)
FDA_VCC: C20.1 c21.1 L5.2 U3.3(~{PD}) U3.10(VS+)
FDA_VOCM: C16.1 C17.1 J5.1 J5.7 R9.1 U3.7(VOCM)
GND: C6.1 C11.1 C12.2 C13.2 C16.2 C17.2 C20.2 c21.2 C26.2 C27.2 C36.2 C37.2 C38.2 C39.2 C40.2 C44.2 C46.2 C48.2 C51.2 C52.2 J2.7 J4.7 R1.1 R2.1 R16.1 R17.1 R25.1 R29.1 R32.1 S1.2 S1.3 S1.4 S1.5 S2.2 S2.3 S2.4 S2.5 S3.2 S3.3 S3.4 S3.5 S4.2 S4.3 S4.4 S4.5 T1.2 T1.5(NC) U2.4(V-) U3.5(VS-) U5.1(DRGND) U5.9(AGND) U5.12(AGND) U5.14(AGND) U5.17(AGND) U5.19(AGND) U5.25(AGND) U5.36(DRGND) U5.49(DRGND)
OPA_VCC: C12.1 C13.1 L4.2 U2.8(V+)
~{ADC_SEN}: U5.27(SEN) ; port ~{ADC_SEN}
ACLKOUT_N: U5.4(CLKOUTM/UNUSED) ; port ACLKOUT_N
ACLKOUT_P: U5.5(CLKOUTP/CLKOUT) ; port ACLKOUT_P
AD0_AD1_N: U5.33(D0_D1_M/D0) ; port AD0_AD1_N
AD0_AD1_P: U5.34(D0_D1_P/D1) ; port AD0_AD1_P
AD2_AD3_N: U5.37(D2_D3_M/D2) ; port AD2_AD3_N
AD2_AD3_P: U5.38(D2_D3_P/D3) ; port AD2_AD3_P
AD4_AD5_N: U5.39(D4_D5_M/D4) ; port AD4_AD5_N
AD4_AD5_P: U5.40(D4_D5_P/D5) ; port AD4_AD5_P
AD6_AD7_N: U5.41(D6_D7_M/D6) ; port AD6_AD7_N
AD6_AD7_P: U5.42(D6_D7_P/D7) ; port AD6_AD7_P
AD8_AD9_N: U5.43(D8_D9_M/D8) ; port AD8_AD9_N
AD8_AD9_P: U5.44(D8_D9_P/D9) ; port AD8_AD9_P
AD10_AD11_N: U5.45(D10_D11_M/D10) ; port AD10_AD11_N
AD10_AD11_P: U5.46(D10_D11_P/D11) ; port AD10_AD11_P
AD12_AD13_N: U5.47(D12_D13_M/D12) ; port AD12_AD13_N
AD12_AD13_P: U5.48(D12_D13_P/D13) ; port AD12_AD13_P
ADC_DFS: J4.2 J4.4 J4.6 J4.8 U5.6(DFS) ; port ADC_DFS
ADC_OVR: U5.3(OVR_SDOUT) ; port ADC_OVR
ADC_SCLK: U5.29(SCLK) ; port ADC_SCLK
ADC_SDI: U5.28(SDATA) ; port ADC_SDI
ADC_VCM: C40.1 R9.2 U5.13(VCM)
ADCIN_N: R21.2 U5.16(INM)
ADCIN_P: R22.2 U5.15(INP)
CLK_N: C43.1 R24.1 U5.11(CLKM) ; port CLK_N
CLK_P: C45.1 R24.2 U5.10(CLKP) ; port CLK_P
FDA_VIN_N: C15.1 C18.2 R7.2 R10.1 U3.6(VIN-)
FDA_VIN_P: C15.2 C19.2 R8.2 R11.1 U3.4(VIN+)
FDAOUT_N: C19.1 J5.5 R11.2 U3.1(VOUT-)
FDAOUT_P: C18.1 J5.3 R10.2 U3.9(VOUT+)
FILIN_N: J5.6 J5.8 R12.1 ; port FILIN_N
FILIN_P: J5.2 J5.4 R13.1 ; port FILIN_P
FILOUT_N: C26.1 C35.2 R12.2 R18.1 R21.1
FILOUT_P: C27.1 C35.1 R13.2 R18.2 R22.1
OPAIN_N: J2.6 J2.8 U2.5(IN+)
OPAIN_P: J2.2 J2.4 U2.3(IN+)
OPAOUT_N: R7.1 U2.6(IN-) U2.7(OUT)
OPAOUT_P: R8.1 U2.1(OUT) U2.2(IN-)
RESET: R29.2 U5.30(RESET)
SIGNAL_IN: C3.2 R1.2 S2.1
V_OFFSET: L2.1 S1.1
NetC3_1: C3.1 R2.2 R3.1 R5.1
NetC6_2: C6.2 C11.2 J2.1 J2.5 R4.2
NetC34_1: C34.1 R19.1
NetC34_2: C34.2 R17.2 S3.1
NetC43_2: C43.2 DA2.3(C) R20.1 T1.4
NetC44_1: C44.1 R20.2 R26.1
NetC45_2: C45.2 DA2.1(A) DA2.2(K) R26.2 T1.6
NetC49_1: C49.1 R27.1
NetC49_2: C49.2 R32.2 S4.1
NetJ2_3: J2.3 R5.2
NetJ4_3: J4.3 R14.1 R15.2
NetJ4_5: J4.5 R15.1 R16.2
NetL2_2: L2.2 R4.1
NetR19_2: R19.2 T1.3
NetR25_2: R25.2 R27.2 T1.1
NetR28_1: R28.1 U5.7(OE)

Not connected (* = marked no-connect by the designer): U3 2(NC)* 8(NC)*; U5 21(NC)* 23(RESERVED)* 31(NC)* 32(NC)*

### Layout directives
differential pair: ACLKOUT_N, ACLKOUT_P, AD0_AD1_N, AD0_AD1_P, AD2_AD3_N, AD2_AD3_P, AD4_AD5_N, AD4_AD5_P, AD6_AD7_N, AD6_AD7_P, AD8_AD9_N, AD8_AD9_P, AD10_AD11_N, AD10_AD11_P, AD12_AD13_N, AD12_AD13_P, ADCIN_N, ADCIN_P, CLK_N, CLK_P, FDA_VIN_N, FDA_VIN_P, FDAOUT_N, FDAOUT_P, FILIN_N, FILIN_P, FILOUT_N, FILOUT_P, OPAIN_N, OPAIN_P, OPAOUT_N, OPAOUT_P

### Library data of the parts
C3 C13 C20 C34 C36-C39 C43-C46 C48 C49 C51 C52 = GRM155R71C104KA88D: as C8 on sheet TIDA-01403_E1_SchSheet_2
C6 C11 = LMK316AB7226KL-TR: CAP, CERM, 22 µF, 10 V, +/- 10%, X7R, 1206; Manufacturer: Taiyo Yuden; Polarized: N; CompType: Capacitor; Value: 22uF; U/M: EA; Cap_F: 0.000022; Tolerance_%: 10; Value1: Unknown; Value2: 10V; TaMin_C: -55; TaMax_C: 125; Cap_Case: 1206; SizeArea_mm2: 5.12; SizeAreaWB_mm2: 10.92; SizeX_mm: 3.2; SizeY_mm: 1.6; SizeZ_mm: 1.8; AEC Category: Q200
C12 c21 = GRM155R61C475ME15: CAP, CERM, 4.7 µF, 16 V, +/- 20%, X5R, 0402; Manufacturer: Samsung Electro-Mechanics; Polarized: N; CompType: Capacitor; Value: 4.7uF; U/M: EA; Cap_F: 0.0000047; Tolerance_%: 20; Value1: Unknown; VDC_V: 16; Value2: 16V; TaMin_C: -55; TaMax_C: 85; Cap_Case: 0402; SizeArea_mm2: 0.5; SizeAreaWB_mm2: 3; SizeX_mm: 1; SizeZ_mm: 0.6; AEC Category: Q200
C15 = GRM1555C1H130JA01D: CAP, CERM, 13 pF, 50 V, +/- 5%, C0G/NP0, 0402; Manufacturer: MuRata; Polarized: N; CompType: Capacitor; Value: 13pF; U/M: EA; Cap_F: 0.000000000013; Tolerance_%: 5; Value1: Unknown; VDC_V: 50; Value2: 50V; TaMin_C: -55; TaMax_C: 125; Cap_Case: 0402; SizeArea_mm2: 0.5; SizeAreaWB_mm2: 3; SizeX_mm: 1; SizeZ_mm: 0.6; AEC Category: Q200
C16 = GRM155R61E105KA12D: CAP, CERM, 1 µF, 25 V, +/- 10%, X5R, 0402; Manufacturer: MuRata; Polarized: N; CompType: Capacitor; Value: 1uF; U/M: EA; Cap_F: 0.000001; Tolerance_%: 10; Value1: Unknown; VDC_V: 25; Value2: 25V; TaMin_C: -55; TaMax_C: 85; Cap_Case: 0402; SizeArea_mm2: 0.5; SizeAreaWB_mm2: 3; SizeX_mm: 1; SizeZ_mm: 0.6; AEC Category: Q200
C17 C40 = GRM155R71E104KE14D: as C5 on sheet TIDA-01403_E1_SchSheet_2
C18 C19 = GRM1555C1E4R7CA01D: CAP, CERM, 4.7 pF, 25 V, +/- 5%, C0G/NP0, 0402; Manufacturer: MuRata; Polarized: N; CompType: Capacitor; Value: 4.7pF; U/M: EA; Cap_F: 0.0000000000047; Tolerance_%: 5; Value1: Unknown; VDC_V: 25; Value2: 25V; TaMin_C: -55; TaMax_C: 125; Cap_Case: 0402; SizeArea_mm2: 0.5; SizeAreaWB_mm2: 3; SizeX_mm: 1; SizeZ_mm: 0.6; AEC Category: Q200
C26 C27 = 885012005043: CAP, CERM, 33 pF, 25 V,+/- 5%, C0G/NP0, 0402; Manufacturer: Wurth Elektronik; Polarized: N; CompType: Capacitor; Value: 33pF; U/M: EA; Cap_F: 0.000000000033; Tolerance_%: 5; VDC_V: 25; Value2: 25V; TaMin_C: -55; TaMax_C: 125; Cap_Case: 0402; SizeArea_mm2: 0.5; SizeAreaWB_mm2: 3; SizeX_mm: 1; SizeZ_mm: 0.6; AEC Category: Q200
C35 = GRM1555C1H560JA01D: CAP, CERM, 56 pF, 50 V, +/- 5%, C0G/NP0, 0402; Manufacturer: MuRata; Polarized: N; CompType: Capacitor; Value: 56pF; U/M: EA; Cap_F: 0.000000000056; Tolerance_%: 5; Value1: Unknown; VDC_V: 50; Value2: 50V; TaMin_C: -55; TaMax_C: 125; Cap_Case: 0402; SizeArea_mm2: 0.5; SizeAreaWB_mm2: 3; SizeX_mm: 1; SizeZ_mm: 0.6; AEC Category: Q200
DA2 = DB3X316F0L: Diode, Schottky, 30 V, 0.1 A, SOT-23; Manufacturer: Panasonic; SymbolCreator: Altium; U/M: EA; Vf_V: 0.55; Value: 30V; Value1: 0.1A; Value2: 0.55V; Io_A: 0.1; Vr_V: 30; TJmax_C: 125; SizeAreaWB_mm2: 14; SizeArea_mm2: 7.5; SizeX_mm: 2.5; SizeY_mm: 3; SizeZ_mm: 1.1; AEC Category: Q101
J2 J4 J5 = GRPB042VWVN-RC: Header, 1.27mm, 4x2, TH; Manufacturer: Sullins Connector Solutions; SymbolCreator: a0411947; Pitch_mm: 1.27; Gender: Male; Shrouded: N; Row_Count: 2; ContactFinish: Gold
L2 L4 L5 L11 = MMZ1005B601CTD25: Ferrite Bead, 600 ohm @ 100 MHz, 0.2 A, 0402; Manufacturer: TDK; Value: 600 ohm; Imax_A: 0.2; DCR_ohm: 0.85; Value1: 0.85 ohm; Value2: 0.2A; SizeAreaWB_mm2: 3; SizeArea_mm2: 0.5; SizeX_mm: 1; SizeZ_mm: 0.6; ZTyp@100MHz_Ohm: 600
R1 R17 R32 = CRCW060350R0FKEA: RES, 50, 1%, 0.1 W, 0603; Manufacturer: Vishay-Dale; CompType: Resistor; Value: 50; Value_Code: 50R0; Tolerance_%: 1; Power_W: 0.1; Value2: 0.1W; VDC_V: 75; TempCo: 100 ppm/C; SizeArea_mm2: 1.28; SizeX_mm: 1.6; SizeY_mm: 0.8; U/M: EA; AEC Category: Q200
R2 R3 = CRCW04022K49FKED: RES, 2.49 k, 1%, 0.063 W, 0402; Manufacturer: Vishay-Dale; CompType: Resistor; Value: 2.49k; Res_ohm: 2490; Value_Code: 2k49; Tolerance_%: 1; Power_W: 0.063; Value2: 0.063W; VDC_V: 50; TempCo: 100 ppm/C; SizeArea_mm2: 0.5; SizeZ_mm: 0.6; EIA_Code: E96; U/M: EA; AEC Category: Q200
R4 R9 = CRCW040210R0FKED: RES, 10.0, 1%, 0.063 W, 0402; Manufacturer: Vishay-Dale; CompType: Resistor; Value: 10.0; Res_ohm: 10; Value_Code: 10R0; Tolerance_%: 1; Power_W: 0.063; Value2: 0.063W; VDC_V: 50; TempCo: 100 ppm/C; SizeArea_mm2: 0.5; SizeZ_mm: 0.6; EIA_Code: E96; U/M: EA; AEC Category: Q200
R5 R19 R21 R22 R25 R27 = ERJ-2GE0R00X: RES, 0, 5%, 0.063 W, 0402; Manufacturer: Panasonic; CompType: Resistor; Value: 0; Value_Code: 0000; Tolerance_%: 5; Power_W: 0.063; Value2: 0.063W; VDC_V: 50; TempCo: 600 ppm/C; SizeArea_mm2: 0.5; SizeX_mm: 1; SizeZ_mm: 0.6; EIA_Code: E24; U/M: EA; AEC Category: Q200
R7 R8 R10 R11 = ERA-2AEB102X: RES, 1.00 k, 0.1%, 0.063 W, 0402; Manufacturer: Panasonic; CompType: Resistor; Value: 1.00k; Res_ohm: 1000; Value_Code: 1k00; Tolerance_%: 0.1; Power_W: 0.063; Value2: 0.063W; VDC_V: 50; TempCo: 25 ppm/C; SizeArea_mm2: 0.5; SizeX_mm: 1; SizeZ_mm: 0.6; EIA_Code: E192; U/M: EA; AEC Category: Q200
R12 R13 = CRCW0402130RFKED: RES, 130, 1%, 0.063 W, 0402; Manufacturer: Vishay-Dale; CompType: Resistor; Value: 130; Value_Code: 130R; Tolerance_%: 1; Power_W: 0.063; Value2: 0.063W; VDC_V: 50; TempCo: 100 ppm/C; SizeArea_mm2: 0.5; SizeZ_mm: 0.6; EIA_Code: E96; U/M: EA; AEC Category: Q200; Green_Lifecycle: Active; Green_REACh: Passed
R14 R16 = CRCW04023K00JNED: RES, 3.0 k, 5%, 0.063 W, 0402; Manufacturer: Vishay-Dale; CompType: Resistor; Value: 3.0k; Res_ohm: 3000; Value_Code: 3k00; Tolerance_%: 5; Power_W: 0.063; Value2: 0.063W; VDC_V: 50; TempCo: 200 ppm/C; SizeArea_mm2: 0.5; SizeX_mm: 1; SizeZ_mm: 0.6; EIA_Code: E24; U/M: EA; AEC Category: Q200
R15 = CRCW04022K00JNED: RES, 2.0 k, 5%, 0.063 W, 0402; Manufacturer: Vishay-Dale; CompType: Resistor; Value: 2.0k; Res_ohm: 2000; Value_Code: 2k00; Tolerance_%: 5; Power_W: 0.063; Value2: 0.063W; VDC_V: 50; TempCo: 200 ppm/C; SizeArea_mm2: 0.5; SizeX_mm: 1; SizeZ_mm: 0.6; EIA_Code: E24; U/M: EA; AEC Category: Q200
R18 = MCR01MRTF1002: RES, 10.0 k, 0.1%, 0.063 W, 0402; Manufacturer: Rohm; CompType: Resistor; Value: 10.0k; Res_ohm: 10000; Value_Code: 10k0; Tolerance_%: 0.1; Power_W: 0.063; Value2: 0.063W; VDC_V: 50; TempCo: 100 ppm/C; SizeArea_mm2: 0.5; SizeX_mm: 1; SizeZ_mm: 0.6; EIA_Code: E192; U/M: EA; AEC Category: Q200; AEC Qualified: N
R20 R24 R26 = CRCW0402100RFKED: RES, 100, 1%, 0.063 W, 0402; Manufacturer: Vishay-Dale; CompType: Resistor; Value: 100; Value_Code: 100R; Tolerance_%: 1; Power_W: 0.063; Value2: 0.063W; VDC_V: 50; TempCo: 100 ppm/C; SizeArea_mm2: 0.5; SizeZ_mm: 0.6; EIA_Code: E96; U/M: EA; AEC Category: Q200
R28 R29 = CRCW040210K0JNED: RES, 10 k, 5%, 0.063 W, 0402; Manufacturer: Vishay-Dale; CompType: Resistor; Value: 10k; Res_ohm: 10000; Value_Code: 10k0; Tolerance_%: 5; Power_W: 0.063; Value2: 0.063W; VDC_V: 50; TempCo: 200 ppm/C; SizeArea_mm2: 0.5; SizeX_mm: 1; SizeZ_mm: 0.6; EIA_Code: E24; U/M: EA; AEC Category: Q200
S1-S4 = 142-0711-821: SMA JACK 50 OHM EDGE MNT, SMT; Manufacturer: Johnson; SymbolCreator: X0208326; Gender: Female; ContactFinish: Gold
SH-J1#2 SH-J2#2 SH-J3-SH-J5 = M50-1900005: CONN SHUNT 1.27MM BLACK; Manufacturer: Harwin
T1 = ADT1-1WT+: RF Transformer, 75 ohm, 0.4 to 800 MHz, SMT; Manufacturer: Minicircuits; SymbolCreator: Altium
U2 = OPA2626IDGKR: High-Speed, High-Precision, Low-Distortion 16-Bit and 18-Bit Analog-to-Digital Converter (ADC) Drivers, DGK0008A (VSSOP-8); Alternate PartNumber: OPA2626IDGKT; Manufacturer: Texas Instruments; CompType: IC; SizeArea_mm2: 15.655; SizeAreaWB_mm2: 35.955; SizeX_mm: 5.05; SizeY_mm: 3.1; SizeZ_mm: 1.1; U/M: EA
U3 = THS4551IRUNR: Low Power, Precision, 160MHz, Fully Differential Amplifier, RUN0010A; Alternate PartNumber: THS4551IRUNT; Manufacturer: Texas Instruments; SymbolCreator: Altium; SizeArea_mm2: 4; SizeAreaWB_mm2: 9; SizeX_mm: 2; SizeZ_mm: 0.8; CompType: IC; U/M: EA
U5 = ADS4142IRGZR: 14-Bit, 65-MSPS, Ultra Low-Power ADC, RGZ0048D (VQFN-48); Alternate PartNumber: ADS4142IRGZT; Manufacturer: Texas Instruments; SymbolCreator: Altium; SizeArea_mm2: 49; SizeAreaWB_mm2: 81; SizeX_mm: 7; SizeZ_mm: 1; CompType: IC; U/M: EA

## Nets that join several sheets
+1V8A: TIDA-01403_E1_SchSheet_2 (C24.1 C29.1 L6.2 TP4.1), TIDA-01403_E1_SchSheet_1 (J4.1 L11.1 R14.2)
+5V0A: TIDA-01403_E1_SchSheet_2 (C4.1 C8.1 L1.2 TP1.1), TIDA-01403_E1_SchSheet_1 (L4.1 L5.1 R3.2)
ADC_DVDD: TIDA-01403_E1_SchSheet_2 (7 pins), TIDA-01403_E1_SchSheet_1 (5 pins)
GND: TIDA-01403_E1_SchSheet_2 (86 pins), TIDA-01403_E1_SchSheet_1 (58 pins)
~{ADC_SEN}: TIDA-01403_E1_SchSheet_2 (C50.1 R31.1), TIDA-01403_E1_SchSheet_1 (U5.27)
ACLKOUT_N: TIDA-01403_E1_SchSheet_2 (R38.2), TIDA-01403_E1_SchSheet_1 (U5.4)
ACLKOUT_P: TIDA-01403_E1_SchSheet_2 (R38.1), TIDA-01403_E1_SchSheet_1 (U5.5)
AD0_AD1_N: TIDA-01403_E1_SchSheet_2 (R37.8), TIDA-01403_E1_SchSheet_1 (U5.33)
AD0_AD1_P: TIDA-01403_E1_SchSheet_2 (R37.7), TIDA-01403_E1_SchSheet_1 (U5.34)
AD2_AD3_N: TIDA-01403_E1_SchSheet_2 (R37.6), TIDA-01403_E1_SchSheet_1 (U5.37)
AD2_AD3_P: TIDA-01403_E1_SchSheet_2 (R37.5), TIDA-01403_E1_SchSheet_1 (U5.38)
AD4_AD5_N: TIDA-01403_E1_SchSheet_2 (R37.4), TIDA-01403_E1_SchSheet_1 (U5.39)
AD4_AD5_P: TIDA-01403_E1_SchSheet_2 (R37.3), TIDA-01403_E1_SchSheet_1 (U5.40)
AD6_AD7_N: TIDA-01403_E1_SchSheet_2 (R37.2), TIDA-01403_E1_SchSheet_1 (U5.41)
AD6_AD7_P: TIDA-01403_E1_SchSheet_2 (R37.1), TIDA-01403_E1_SchSheet_1 (U5.42)
AD8_AD9_N: TIDA-01403_E1_SchSheet_2 (R38.8), TIDA-01403_E1_SchSheet_1 (U5.43)
AD8_AD9_P: TIDA-01403_E1_SchSheet_2 (R38.7), TIDA-01403_E1_SchSheet_1 (U5.44)
AD10_AD11_N: TIDA-01403_E1_SchSheet_2 (R38.6), TIDA-01403_E1_SchSheet_1 (U5.45)
AD10_AD11_P: TIDA-01403_E1_SchSheet_2 (R38.5), TIDA-01403_E1_SchSheet_1 (U5.46)
AD12_AD13_N: TIDA-01403_E1_SchSheet_2 (R38.4), TIDA-01403_E1_SchSheet_1 (U5.47)
AD12_AD13_P: TIDA-01403_E1_SchSheet_2 (R38.3), TIDA-01403_E1_SchSheet_1 (U5.48)
ADC_OVR: TIDA-01403_E1_SchSheet_2 (J7.6), TIDA-01403_E1_SchSheet_1 (U5.3)
ADC_SCLK: TIDA-01403_E1_SchSheet_2 (C54.1 R36.1), TIDA-01403_E1_SchSheet_1 (U5.29)
ADC_SDI: TIDA-01403_E1_SchSheet_2 (C53.1 R34.1), TIDA-01403_E1_SchSheet_1 (U5.28)

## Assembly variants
001: not fitted FID1 FID2 FID3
